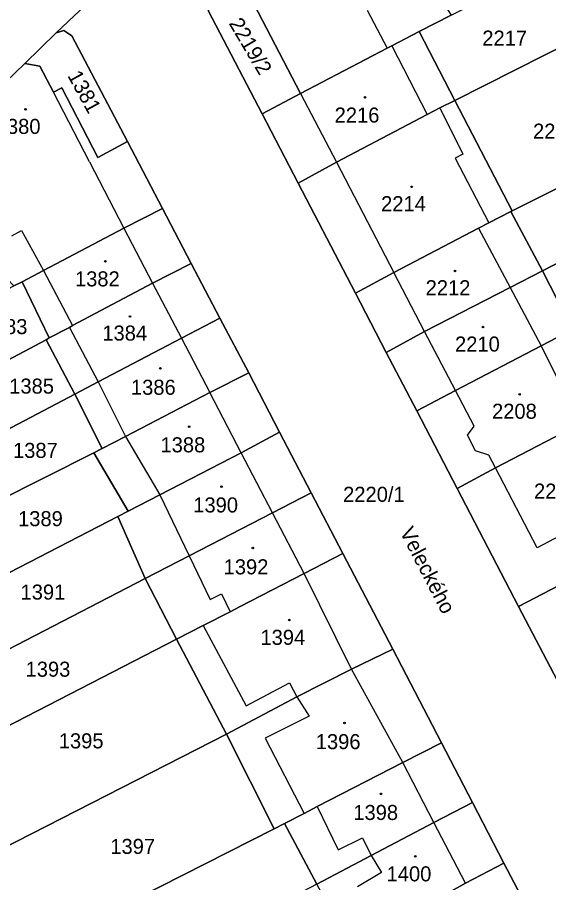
# Model space of a CAD drawing. Extents: x -596233 to -595156, y -1161235 to -1159375.
# Drawn here: x -595977.1 to -595917.1, y -1160689.1 to -1160591.4 of the extents above; entities that cross this region are included whole.
import ezdxf

# ---------------------------------------------------------------- set-up
doc = ezdxf.new("R2010")
doc.units = 0
for name, color, linetype in [('KN_CAR_KR', 7, 'Continuous'), ('KN_KULTURY', 7, 'Continuous'), ('KN_PARC_CIS_POZ', 7, 'Continuous'), ('KN_PARC_CIS_STAV', 7, 'Continuous'), ('KN_PARC_PLOCHA', 7, 'Continuous'), ('KN_ULICE', 7, 'Continuous'), ('parcely_l', 7, 'Continuous')]:
    doc.layers.add(name, color=color, linetype=linetype)

msp = doc.modelspace()

# ---------------------------------------------------------------- linework, layer by layer
at = {"layer": 'KN_CAR_KR'}
for points in [[(-595937.6, -1160590.53), (-595935.36, -1160594.84)], [(-595934.83, -1160594.56), (-595930.81, -1160602.33)], [(-595968.96, -1160607.68), (-595973.04, -1160599.82)], [(-595945.12, -1160599.94), (-595941.08, -1160607.7)], [(-595929.39, -1160601.59), (-595926.78, -1160606.79)], [(-595926.78, -1160606.79), (-595927.67, -1160607.25)], [(-595968.96, -1160607.68), (-595965.08, -1160615.16)], [(-595941.08, -1160607.7), (-595934.58, -1160620.16)], [(-595927.67, -1160607.25), (-595923.87, -1160614.55)], [(-595977.73, -1160616.03), (-595976.64, -1160615.43)], [(-595976.64, -1160615.43), (-595974.16, -1160619.93)], [(-595965.08, -1160615.16), (-595961.84, -1160621.39)], [(-595925.02, -1160615.15), (-595921.44, -1160621.85)], [(-595974.16, -1160619.93), (-595970.89, -1160626.15)], [(-595931.11, -1160626.83), (-595934.58, -1160620.16)], [(-595961.84, -1160621.39), (-595958.56, -1160627.59)], [(-595921.44, -1160621.85), (-595917.95, -1160628.46)], [(-595971.24, -1160626.39), (-595967.98, -1160632.52)], [(-595927.63, -1160633.5), (-595931.11, -1160626.83)], [(-595958.56, -1160627.59), (-595955.38, -1160633.73)], [(-595917.95, -1160628.46), (-595914.82, -1160634.73)], [(-595967.98, -1160632.52), (-595964.91, -1160638.69)], [(-595951.84, -1160640.52), (-595955.38, -1160633.73)], [(-595925.53, -1160637.54), (-595927.63, -1160633.5)], [(-595926.28, -1160638.54), (-595925.53, -1160637.54)], [(-595964.91, -1160638.69), (-595961.03, -1160645.28)], [(-595925.36, -1160640.32), (-595926.28, -1160638.54)], [(-595948.3, -1160647.31), (-595951.84, -1160640.52)], [(-595923.84, -1160640.8), (-595925.36, -1160640.32)], [(-595923.09, -1160642.23), (-595923.84, -1160640.8)], [(-595918.41, -1160651.25), (-595923.09, -1160642.23)], [(-595961.03, -1160645.28), (-595957.7, -1160652.18)], [(-595944.71, -1160654.17), (-595948.3, -1160647.31)], [(-595913.99, -1160648.92), (-595918.41, -1160651.25)], [(-595957.7, -1160652.18), (-595955.33, -1160657.09)], [(-595939.36, -1160664.97), (-595944.71, -1160654.17)], [(-595955.33, -1160657.09), (-595954.05, -1160656.47)], [(-595954.05, -1160656.47), (-595953.09, -1160658.48)], [(-595956.11, -1160660.03), (-595951.28, -1160669.11)], [(-595933.59, -1160675.52), (-595939.36, -1160664.97)], [(-595951.28, -1160669.11), (-595946.37, -1160666.5)], [(-595946.37, -1160666.5), (-595945.53, -1160668.09)], [(-595945.53, -1160668.09), (-595944.16, -1160670.29)], [(-595944.16, -1160670.29), (-595949.14, -1160672.75)], [(-595949.14, -1160672.75), (-595944.71, -1160681.25)], [(-595930.06, -1160682.29), (-595933.59, -1160675.52)], [(-595943.24, -1160680.49), (-595940.86, -1160685.37)], [(-595926.5, -1160689.12), (-595930.06, -1160682.29)], [(-595940.86, -1160685.37), (-595938.11, -1160684.02)], [(-595938.11, -1160684.02), (-595937.14, -1160686.01)], [(-595937.14, -1160686.01), (-595935.99, -1160687.94)], [(-595935.99, -1160687.94), (-595938.69, -1160689.55)]]:
    msp.add_lwpolyline(points, dxfattribs=at)
at = {"layer": 'KN_KULTURY'}
for centre, radius in [((-595937.85, -1160600.39), 0.09), ((-595937.85, -1160600.39), 0.0398), ((-595976.19, -1160601.74), 0.09), ((-595976.19, -1160601.74), 0.0398), ((-595932.57, -1160610.5), 0.09), ((-595932.57, -1160610.5), 0.0398), ((-595967.17, -1160618.9), 0.09), ((-595967.17, -1160618.9), 0.0398), ((-595927.68, -1160619.99), 0.09), ((-595927.68, -1160619.99), 0.0398), ((-595964.39, -1160625.14), 0.09), ((-595964.39, -1160625.14), 0.0398), ((-595924.51, -1160626.33), 0.09), ((-595924.51, -1160626.33), 0.0398), ((-595960.96, -1160631), 0.09), ((-595960.96, -1160631), 0.0398), ((-595920.37, -1160633.93), 0.09), ((-595920.37, -1160633.93), 0.0398), ((-595957.71, -1160637.58), 0.09), ((-595957.71, -1160637.58), 0.0398), ((-595954.05, -1160644.36), 0.09), ((-595954.05, -1160644.36), 0.0398), ((-595950.52, -1160651.28), 0.09), ((-595950.52, -1160651.28), 0.0398), ((-595946.39, -1160659.42), 0.09), ((-595946.39, -1160659.42), 0.0398), ((-595940.16, -1160671.05), 0.09), ((-595940.16, -1160671.05), 0.0398), ((-595936.03, -1160679.05), 0.09), ((-595936.03, -1160679.05), 0.0398), ((-595932.17, -1160686.11), 0.09), ((-595932.17, -1160686.11), 0.0398)]:
    msp.add_circle(centre, radius, dxfattribs=at)
at = {"layer": 'KN_PARC_PLOCHA'}
for points in [[(-595851.78, -1160477.77), (-595858.23, -1160483.86), (-595869.29, -1160494.3), (-595869.41, -1160494.3), (-595887.17, -1160511.46), (-595890, -1160514.14), (-595899.73, -1160523.37), (-595904.69, -1160528.17), (-595909.08, -1160532.42), (-595918.49, -1160541.47), (-595925.61, -1160548.26), (-595928.68, -1160551.19), (-595935.8, -1160557.97), (-595941.36, -1160563.28), (-595947.04, -1160568.69), (-595959.29, -1160580.37), (-595972.74, -1160593.11), (-595976.26, -1160596.57), (-595989.4, -1160609.23)], [(-595918.63, -1160693.63), (-595922.15, -1160686.88), (-595925.71, -1160680.03), (-595929.22, -1160673.3), (-595934.71, -1160662.72), (-595940.36, -1160651.9), (-595943.91, -1160645.07), (-595947.49, -1160638.19), (-595950.98, -1160631.49), (-595954.23, -1160625.32), (-595957.48, -1160619.14), (-595960.73, -1160612.94), (-595964.69, -1160605.39), (-595970.95, -1160593.45), (-595971.86, -1160592.85), (-595972.74, -1160593.11), (-595959.29, -1160580.37)], [(-595955.55, -1160590.59), (-595949.46, -1160602.27), (-595945.4, -1160610.08), (-595938.93, -1160622.5), (-595935.44, -1160629.19), (-595932, -1160635.8), (-595927.43, -1160644.58), (-595920.5, -1160657.89), (-595914.93, -1160668.51), (-595912.07, -1160673.95), (-595909.16, -1160679.49), (-595906.25, -1160685.05), (-595903.39, -1160690.49)]]:
    msp.add_lwpolyline(points, dxfattribs=at)
for points in [[(-595930.07, -1160587.76), (-595929.48, -1160588.96), (-595928.1, -1160591.1), (-595931.73, -1160592.94), (-595934.83, -1160594.56), (-595935.36, -1160594.84), (-595945.12, -1160599.94), (-595951.84, -1160587.04), (-595940.17, -1160575.85), (-595932.67, -1160583.79), (-595931.47, -1160585.06)], [(-595910.73, -1160592.17), (-595927.71, -1160600.76), (-595931.73, -1160592.94), (-595928.1, -1160591.1), (-595921.51, -1160587.76), (-595914.88, -1160584.4)], [(-595945.12, -1160599.94), (-595949.46, -1160602.27), (-595955.55, -1160590.59), (-595951.84, -1160587.04)], [(-595904.1, -1160604.62), (-595921.23, -1160613.22), (-595927.71, -1160600.76), (-595910.73, -1160592.17)], [(-595964.69, -1160605.39), (-595968.02, -1160607.19), (-595972.1, -1160599.33), (-595973.04, -1160599.82), (-595974.57, -1160596.88), (-595976.26, -1160596.57), (-595972.74, -1160593.11), (-595971.86, -1160592.85), (-595970.95, -1160593.45)], [(-595927.71, -1160600.76), (-595929.39, -1160601.59), (-595930.81, -1160602.33), (-595941.08, -1160607.7), (-595945.4, -1160610.08), (-595949.46, -1160602.27), (-595945.12, -1160599.94), (-595935.36, -1160594.84), (-595934.83, -1160594.56), (-595931.73, -1160592.94)], [(-595964.69, -1160605.39), (-595960.73, -1160612.94), (-595965.08, -1160615.16), (-595974.16, -1160619.93), (-595976.59, -1160621.21), (-595977.52, -1160621.69), (-595982.56, -1160616.4), (-595983.32, -1160615.6), (-595989.4, -1160609.23), (-595976.26, -1160596.57), (-595974.57, -1160596.88), (-595973.04, -1160599.82), (-595972.1, -1160599.33), (-595968.02, -1160607.19)], [(-595921.23, -1160613.22), (-595921.37, -1160613.3), (-595923.87, -1160614.55), (-595925.02, -1160615.15), (-595934.58, -1160620.16), (-595938.93, -1160622.5), (-595945.4, -1160610.08), (-595941.08, -1160607.7), (-595930.81, -1160602.33), (-595929.39, -1160601.59), (-595927.71, -1160600.76)], [(-595900.63, -1160611.15), (-595917.79, -1160619.98), (-595921.37, -1160613.3), (-595921.23, -1160613.22), (-595904.1, -1160604.62)], [(-595893.38, -1160615.67), (-595914.4, -1160626.61), (-595917.79, -1160619.98), (-595900.63, -1160611.15), (-595896.51, -1160609.35)], [(-595957.48, -1160619.14), (-595961.84, -1160621.39), (-595970.89, -1160626.15), (-595971.24, -1160626.39), (-595973.54, -1160627.55), (-595976.59, -1160621.21), (-595974.16, -1160619.93), (-595965.08, -1160615.16), (-595960.73, -1160612.94)], [(-595917.79, -1160619.98), (-595921.44, -1160621.85), (-595931.11, -1160626.83), (-595935.44, -1160629.19), (-595938.93, -1160622.5), (-595934.58, -1160620.16), (-595925.02, -1160615.15), (-595923.87, -1160614.55), (-595921.37, -1160613.3)], [(-595954.23, -1160625.32), (-595958.56, -1160627.59), (-595967.98, -1160632.52), (-595970.62, -1160633.91), (-595973.86, -1160627.78), (-595973.54, -1160627.55), (-595971.24, -1160626.39), (-595970.89, -1160626.15), (-595961.84, -1160621.39), (-595957.48, -1160619.14)], [(-595914.4, -1160626.61), (-595917.95, -1160628.46), (-595927.63, -1160633.5), (-595932, -1160635.8), (-595935.44, -1160629.19), (-595931.11, -1160626.83), (-595921.44, -1160621.85), (-595917.79, -1160619.98)], [(-595973.54, -1160627.55), (-595973.86, -1160627.78), (-595978.83, -1160630.42), (-595983.96, -1160625.08), (-595977.52, -1160621.69), (-595976.59, -1160621.21)], [(-595950.98, -1160631.49), (-595955.38, -1160633.73), (-595964.91, -1160638.69), (-595967.52, -1160640.05), (-595970.62, -1160633.91), (-595967.98, -1160632.52), (-595958.56, -1160627.59), (-595954.23, -1160625.32)], [(-595909.97, -1160635.41), (-595912.11, -1160636.52), (-595912.67, -1160636.81), (-595923.09, -1160642.23), (-595927.43, -1160644.58), (-595932, -1160635.8), (-595927.63, -1160633.5), (-595917.95, -1160628.46), (-595914.4, -1160626.61)], [(-595970.62, -1160633.91), (-595979.17, -1160638.39), (-595978.83, -1160630.42), (-595973.86, -1160627.78)], [(-595947.49, -1160638.19), (-595951.84, -1160640.52), (-595961.03, -1160645.28), (-595964.6, -1160647.13), (-595968.46, -1160640.54), (-595967.52, -1160640.05), (-595964.91, -1160638.69), (-595955.38, -1160633.73), (-595950.98, -1160631.49)], [(-595967.52, -1160640.05), (-595968.46, -1160640.54), (-595979.5, -1160646.08), (-595979.34, -1160642.38), (-595979.17, -1160638.39), (-595970.62, -1160633.91)], [(-595902.08, -1160648.28), (-595905.59, -1160650.12), (-595906.69, -1160650.69), (-595920.5, -1160657.89), (-595927.43, -1160644.58), (-595923.09, -1160642.23), (-595912.67, -1160636.81), (-595912.11, -1160636.52), (-595909.97, -1160635.41), (-595909.03, -1160634.92), (-595903.64, -1160645.3)], [(-595877.14, -1160648.64), (-595898.34, -1160659.73), (-595898.69, -1160659.92), (-595899.69, -1160660.44), (-595902.51, -1160655.03), (-595905.28, -1160656.43), (-595905.61, -1160655.78), (-595908.58, -1160657.3), (-595909.22, -1160656.05), (-595912.6, -1160657.79), (-595911.96, -1160659.03), (-595913.76, -1160659.94), (-595910.53, -1160666.12), (-595914.93, -1160668.51), (-595920.5, -1160657.89), (-595906.69, -1160650.69), (-595905.17, -1160653.6), (-595900.53, -1160651.24), (-595902.08, -1160648.28), (-595882.32, -1160637.89)], [(-595943.91, -1160645.07), (-595948.3, -1160647.31), (-595957.7, -1160652.18), (-595962.67, -1160654.73), (-595965.78, -1160647.74), (-595964.6, -1160647.13), (-595961.03, -1160645.28), (-595951.84, -1160640.52), (-595947.49, -1160638.19)], [(-595964.6, -1160647.13), (-595965.78, -1160647.74), (-595977.99, -1160654.06), (-595981.97, -1160647.35), (-595979.5, -1160646.08), (-595968.46, -1160640.54)], [(-595940.36, -1160651.9), (-595944.71, -1160654.17), (-595952.02, -1160657.93), (-595953.09, -1160658.48), (-595956.11, -1160660.03), (-595959.13, -1160661.59), (-595962.67, -1160654.73), (-595957.7, -1160652.18), (-595948.3, -1160647.31), (-595943.91, -1160645.07)], [(-595962.67, -1160654.73), (-595983.41, -1160665.45), (-595989, -1160659.76), (-595977.99, -1160654.06), (-595965.78, -1160647.74)], [(-595934.71, -1160662.72), (-595939.36, -1160664.97), (-595945.53, -1160668.09), (-595953.49, -1160672.31), (-595959.13, -1160661.59), (-595956.11, -1160660.03), (-595953.09, -1160658.48), (-595952.02, -1160657.93), (-595944.71, -1160654.17), (-595940.36, -1160651.9)], [(-595959.13, -1160661.59), (-595984.53, -1160674.64), (-595989.94, -1160668.83), (-595983.41, -1160665.45), (-595962.67, -1160654.73)], [(-595953.49, -1160672.31), (-595982.34, -1160687.03), (-595986.98, -1160682.2), (-595991.02, -1160677.98), (-595984.53, -1160674.64), (-595959.13, -1160661.59)], [(-595929.22, -1160673.3), (-595933.59, -1160675.52), (-595943.24, -1160680.49), (-595944.71, -1160681.25), (-595946.95, -1160682.4), (-595948.11, -1160683), (-595953.49, -1160672.31), (-595945.53, -1160668.09), (-595939.36, -1160664.97), (-595934.71, -1160662.72)], [(-595948.11, -1160683), (-595976.52, -1160697.42), (-595978.29, -1160694.27), (-595982.34, -1160687.03), (-595953.49, -1160672.31)], [(-595925.71, -1160680.03), (-595930.06, -1160682.29), (-595937.14, -1160686.01), (-595943.3, -1160689.24), (-595946.95, -1160682.4), (-595944.71, -1160681.25), (-595943.24, -1160680.49), (-595933.59, -1160675.52), (-595929.22, -1160673.3)], [(-595922.15, -1160686.88), (-595926.5, -1160689.12), (-595935.82, -1160694.38), (-595939.69, -1160695.99), (-595943.3, -1160689.24), (-595937.14, -1160686.01), (-595930.06, -1160682.29), (-595925.71, -1160680.03)], [(-595943.3, -1160689.24), (-595972.52, -1160704.58), (-595973.87, -1160702.17), (-595976.52, -1160697.42), (-595948.11, -1160683), (-595946.95, -1160682.4)], [(-595918.63, -1160693.63), (-595922.96, -1160695.91), (-595931.73, -1160700.46), (-595932.62, -1160700.92), (-595934.83, -1160702.09), (-595936.15, -1160702.78), (-595939.69, -1160695.99), (-595935.82, -1160694.38), (-595926.5, -1160689.12), (-595922.15, -1160686.88)]]:
    msp.add_lwpolyline(points, close=True, dxfattribs=at)
at = {"layer": 'parcely_l'}
for points in [[(-595972.74, -1160593.11), (-595959.29, -1160580.37)], [(-595951.84, -1160587.04), (-595945.12, -1160599.94)], [(-595955.55, -1160590.59), (-595949.46, -1160602.27)], [(-595931.73, -1160592.94), (-595928.1, -1160591.1)], [(-595910.73, -1160592.17), (-595927.71, -1160600.76)], [(-595976.26, -1160596.57), (-595972.74, -1160593.11)], [(-595972.74, -1160593.11), (-595971.86, -1160592.85), (-595970.95, -1160593.45), (-595964.69, -1160605.39)], [(-595931.73, -1160592.94), (-595934.83, -1160594.56), (-595935.36, -1160594.84), (-595945.12, -1160599.94)], [(-595927.71, -1160600.76), (-595931.73, -1160592.94)], [(-595976.26, -1160596.57), (-595989.4, -1160609.23)], [(-595964.69, -1160605.39), (-595968.02, -1160607.19), (-595972.1, -1160599.33), (-595973.04, -1160599.82), (-595974.57, -1160596.88), (-595976.26, -1160596.57)], [(-595945.12, -1160599.94), (-595949.46, -1160602.27)], [(-595945.4, -1160610.08), (-595941.08, -1160607.7), (-595930.81, -1160602.33), (-595929.39, -1160601.59), (-595927.71, -1160600.76)], [(-595927.71, -1160600.76), (-595921.23, -1160613.22)], [(-595949.46, -1160602.27), (-595945.4, -1160610.08)], [(-595904.1, -1160604.62), (-595921.23, -1160613.22)], [(-595960.73, -1160612.94), (-595964.69, -1160605.39)], [(-595945.4, -1160610.08), (-595938.93, -1160622.5)], [(-595917.79, -1160619.98), (-595900.63, -1160611.15)], [(-595976.59, -1160621.21), (-595974.16, -1160619.93), (-595965.08, -1160615.16), (-595960.73, -1160612.94)], [(-595957.48, -1160619.14), (-595960.73, -1160612.94)], [(-595921.37, -1160613.3), (-595923.87, -1160614.55), (-595925.02, -1160615.15), (-595934.58, -1160620.16), (-595938.93, -1160622.5)], [(-595921.23, -1160613.22), (-595921.37, -1160613.3)], [(-595917.79, -1160619.98), (-595921.37, -1160613.3)], [(-595957.48, -1160619.14), (-595961.84, -1160621.39), (-595970.89, -1160626.15), (-595971.24, -1160626.39), (-595973.54, -1160627.55)], [(-595954.23, -1160625.32), (-595957.48, -1160619.14)], [(-595935.44, -1160629.19), (-595931.11, -1160626.83), (-595921.44, -1160621.85), (-595917.79, -1160619.98)], [(-595914.4, -1160626.61), (-595917.79, -1160619.98)], [(-595977.52, -1160621.69), (-595976.59, -1160621.21)], [(-595973.54, -1160627.55), (-595976.59, -1160621.21)], [(-595938.93, -1160622.5), (-595935.44, -1160629.19)], [(-595970.62, -1160633.91), (-595967.98, -1160632.52), (-595958.56, -1160627.59), (-595954.23, -1160625.32)], [(-595954.23, -1160625.32), (-595950.98, -1160631.49)], [(-595932, -1160635.8), (-595927.63, -1160633.5), (-595917.95, -1160628.46), (-595914.4, -1160626.61)], [(-595973.86, -1160627.78), (-595978.83, -1160630.42)], [(-595973.54, -1160627.55), (-595973.86, -1160627.78)], [(-595973.86, -1160627.78), (-595970.62, -1160633.91)], [(-595935.44, -1160629.19), (-595932, -1160635.8)], [(-595950.98, -1160631.49), (-595955.38, -1160633.73), (-595964.91, -1160638.69), (-595967.52, -1160640.05)], [(-595947.49, -1160638.19), (-595950.98, -1160631.49)], [(-595970.62, -1160633.91), (-595979.17, -1160638.39)], [(-595967.52, -1160640.05), (-595970.62, -1160633.91)], [(-595932, -1160635.8), (-595927.43, -1160644.58)], [(-595909.97, -1160635.41), (-595912.11, -1160636.52), (-595912.67, -1160636.81), (-595923.09, -1160642.23), (-595927.43, -1160644.58)], [(-595964.6, -1160647.13), (-595961.03, -1160645.28), (-595951.84, -1160640.52), (-595947.49, -1160638.19)], [(-595943.91, -1160645.07), (-595947.49, -1160638.19)], [(-595967.52, -1160640.05), (-595968.46, -1160640.54)], [(-595979.5, -1160646.08), (-595968.46, -1160640.54)], [(-595968.46, -1160640.54), (-595964.6, -1160647.13)], [(-595927.43, -1160644.58), (-595920.5, -1160657.89)], [(-595943.91, -1160645.07), (-595948.3, -1160647.31), (-595957.7, -1160652.18), (-595962.67, -1160654.73)], [(-595940.36, -1160651.9), (-595943.91, -1160645.07)], [(-595977.99, -1160654.06), (-595965.78, -1160647.74)], [(-595964.6, -1160647.13), (-595965.78, -1160647.74)], [(-595965.78, -1160647.74), (-595962.67, -1160654.73)], [(-595920.5, -1160657.89), (-595906.69, -1160650.69)], [(-595959.13, -1160661.59), (-595956.11, -1160660.03), (-595953.09, -1160658.48), (-595952.02, -1160657.93), (-595944.71, -1160654.17), (-595940.36, -1160651.9)], [(-595934.71, -1160662.72), (-595940.36, -1160651.9)], [(-595962.67, -1160654.73), (-595983.41, -1160665.45)], [(-595959.13, -1160661.59), (-595962.67, -1160654.73)], [(-595920.5, -1160657.89), (-595914.93, -1160668.51)], [(-595984.53, -1160674.64), (-595959.13, -1160661.59)], [(-595959.13, -1160661.59), (-595953.49, -1160672.31)], [(-595953.49, -1160672.31), (-595945.53, -1160668.09), (-595939.36, -1160664.97), (-595934.71, -1160662.72)], [(-595929.22, -1160673.3), (-595934.71, -1160662.72)], [(-595953.49, -1160672.31), (-595982.34, -1160687.03)], [(-595948.11, -1160683), (-595953.49, -1160672.31)], [(-595946.95, -1160682.4), (-595944.71, -1160681.25), (-595943.24, -1160680.49), (-595933.59, -1160675.52), (-595929.22, -1160673.3)], [(-595929.22, -1160673.3), (-595925.71, -1160680.03)], [(-595925.71, -1160680.03), (-595930.06, -1160682.29), (-595937.14, -1160686.01), (-595943.3, -1160689.24)], [(-595922.15, -1160686.88), (-595925.71, -1160680.03)], [(-595976.52, -1160697.42), (-595948.11, -1160683)], [(-595946.95, -1160682.4), (-595948.11, -1160683)], [(-595943.3, -1160689.24), (-595946.95, -1160682.4)], [(-595939.69, -1160695.99), (-595935.82, -1160694.38), (-595926.5, -1160689.12), (-595922.15, -1160686.88)], [(-595918.63, -1160693.63), (-595922.15, -1160686.88)]]:
    msp.add_lwpolyline(points, dxfattribs=at)

# ---------------------------------------------------------------- texts
at = {"layer": 'KN_PARC_CIS_POZ'}
for s, rotation, p in [('2219/2', 300.616948, (-595953.2731, -1160592.0349)), ('1381', 298.800901, (-595971.5015, -1160597.9289))]:
    msp.add_text(s, height=1.7, rotation=rotation, dxfattribs=at).set_placement(p)
for s, p in [('2217', (-595924.5966, -1160594.55)), ('2215', (-595918.8666, -1160605.06)), ('1383', (-595981.0366, -1160627.13)), ('1385', (-595978.0366, -1160633.85)), ('1387', (-595977.6066, -1160641.11)), ('2220/1', (-595940.3166, -1160646.07)), ('1389', (-595977.0366, -1160648.82)), ('1391', (-595976.7566, -1160657.11)), ('1393', (-595976.1866, -1160665.82)), ('1395', (-595972.4366, -1160673.91)), ('1397', (-595966.6166, -1160685.83))]:
    msp.add_text(s, height=1.7, dxfattribs=at).set_placement(p)
at = {"layer": 'KN_PARC_CIS_STAV'}
for s, p in [('2216', (-595941.2766, -1160603.24)), ('1380', (-595979.5566, -1160604.52)), ('2214', (-595936.0266, -1160613.25)), ('1382', (-595970.6066, -1160621.74)), ('2212', (-595930.9966, -1160622.74)), ('1384', (-595967.5166, -1160627.86)), ('2210', (-595927.6766, -1160629.1)), ('1386', (-595964.2866, -1160633.98)), ('2208', (-595923.4966, -1160636.69)), ('1388', (-595960.9466, -1160640.48)), ('2206', (-595918.7566, -1160645.71)), ('1390', (-595957.2466, -1160647.27)), ('1392', (-595953.8166, -1160654.26)), ('1394', (-595949.6566, -1160662.22)), ('1396', (-595943.4066, -1160674)), ('1398', (-595939.1666, -1160682)), ('1400', (-595935.4066, -1160688.93))]:
    msp.add_text(s, height=1.7, dxfattribs=at).set_placement(p)
at = {"layer": 'KN_ULICE'}
msp.add_text('Veleckého', height=1.7, rotation=297.379009, dxfattribs=at).set_placement((-595933.9577, -1160649.4586))

doc.saveas('drawing.dxf')
